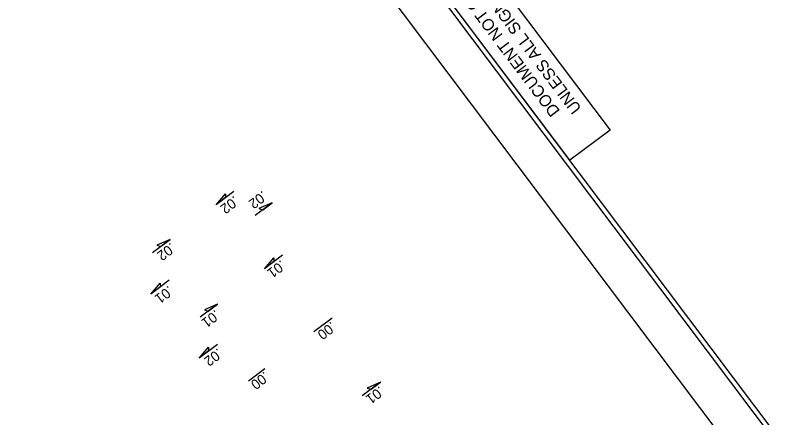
# Model space of a CAD drawing. Extents: x 1263113 to 1265001, y 775064 to 777068.
# Drawn here: x 1263113.4 to 1263498.2, y 775950.8 to 776151.3 of the extents above; entities that cross this region are included whole.
import ezdxf

# ---------------------------------------------------------------- set-up
doc = ezdxf.new("R2010")
doc.units = 0
for name, color, linetype in [('Prop Superelevation  Arrow CELL', 7, 'Continuous'), ('Prop Superelevation Label', 7, 'Continuous'), ('Sheet Plot Border Inside CELL', 7, 'Continuous'), ('Sheet Plot Border Outside CELL', 7, 'Continuous'), ('Sheet Sticker Exception Certification CELL', 7, 'Continuous'), ('Sheet Typical CELL', 7, 'Continuous')]:
    doc.layers.add(name, color=color, linetype=linetype)

msp = doc.modelspace()

# ---------------------------------------------------------------- linework, layer by layer
at = {"layer": 'Prop Superelevation  Arrow CELL'}
for points in [[(1263213.51, 776056.96), (1263218.14, 776062.45), (1263218.22, 776060.51)], [(1263213.51, 776056.96), (1263218.14, 776062.45), (1263218.22, 776060.51)], [(1263241.45, 776057.97), (1263234.89, 776055.04), (1263236.73, 776054.42)], [(1263241.45, 776057.97), (1263234.89, 776055.04), (1263236.73, 776054.42)], [(1263190.53, 776039.65), (1263183.97, 776036.71), (1263185.82, 776036.1)], [(1263237.62, 776025.04), (1263242.25, 776030.53), (1263242.33, 776028.59)], [(1263237.62, 776025.04), (1263242.25, 776030.53), (1263242.33, 776028.59)], [(1263180.99, 776012.43), (1263185.62, 776017.92), (1263185.7, 776015.98)], [(1263214.26, 776007.44), (1263207.7, 776004.51), (1263209.54, 776003.89)], [(1263205.07, 775980.49), (1263209.7, 775985.98), (1263209.78, 775984.04)], [(1263205.07, 775980.49), (1263209.7, 775985.98), (1263209.78, 775984.04)], [(1263295.5, 775968.48), (1263288.95, 775965.55), (1263290.79, 775964.93)], [(1263295.5, 775968.48), (1263288.95, 775965.55), (1263290.79, 775964.93)]]:
    msp.add_lwpolyline(points, close=True, dxfattribs=at)
at = {"layer": 'Prop Superelevation Label'}
for p, q in [((1263222.31, 776063.58), (1263213.51, 776056.96)), ((1263241.45, 776057.97), (1263232.97, 776051.59)), ((1263190.53, 776039.65), (1263181.71, 776033)), ((1263246.65, 776031.84), (1263237.58, 776025.01)), ((1263190.1, 776019.29), (1263181.03, 776012.46)), ((1263214.26, 776007.44), (1263205.52, 776000.86)), ((1263271.34, 776000.36), (1263262.27, 775993.53)), ((1263214.14, 775987.32), (1263205.07, 775980.49)), ((1263237.78, 775975.08), (1263229.68, 775968.98)), ((1263295.5, 775968.48), (1263286.43, 775961.65))]:
    msp.add_line(p, q, dxfattribs=at)
at = {"layer": 'Sheet Plot Border Inside CELL'}
msp.add_lwpolyline([(1264977.07, 775721.54), (1263974.73, 777052.27), (1263132.03, 776417.56), (1264134.37, 775086.81)], close=True, dxfattribs=at)
at = {"layer": 'Sheet Plot Border Outside CELL'}
msp.add_lwpolyline([(1263113.35, 776409.12), (1264126.21, 775064.39), (1265000.86, 775723.19), (1263988, 777067.91)], close=True, dxfattribs=at)
at = {"layer": 'Sheet Sticker Exception Certification CELL'}
for p, q in [((1263281.87, 776264.34), (1263410.06, 776094.15)), ((1263390.06, 776079.1), (1263261.88, 776249.28)), ((1263410.06, 776094.15), (1263390.06, 776079.1))]:
    msp.add_line(p, q, dxfattribs=at)
at = {"layer": 'Sheet Typical CELL'}
msp.add_line((1264044, 775210.92), (1263141.54, 776409.07), dxfattribs=at)

# ---------------------------------------------------------------- texts
at = {"layer": 'Prop Superelevation Label'}
for s, p in [('.02', (1263236.69, 776064.13)), ('.02', (1263222.53, 776061.62)), ('.02', (1263190.93, 776038.25)), ('.01', (1263245.91, 776029.6)), ('.01', (1263189.8, 776016.81)), ('.01', (1263213.11, 776004.8)), ('.00', (1263270.99, 775998.86)), ('.02', (1263214.4, 775985.62)), ('.00', (1263237.69, 775973.99)), ('.01', (1263295.1, 775966.75))]:
    msp.add_text(s, height=5, rotation=217.2584, dxfattribs=at).set_placement(p)
at = {"layer": 'Sheet Sticker Exception Certification CELL'}
for s, p in [('UNLESS ALL SIGNATURES COMPLETED', (1263396.1, 776104.98)), ('DOCUMENT NOT CONSIDERED FINAL', (1263385.36, 776103.65))]:
    msp.add_text(s, height=5.8579, rotation=126.9874, dxfattribs=at).set_placement(p)

doc.saveas('drawing.dxf')
